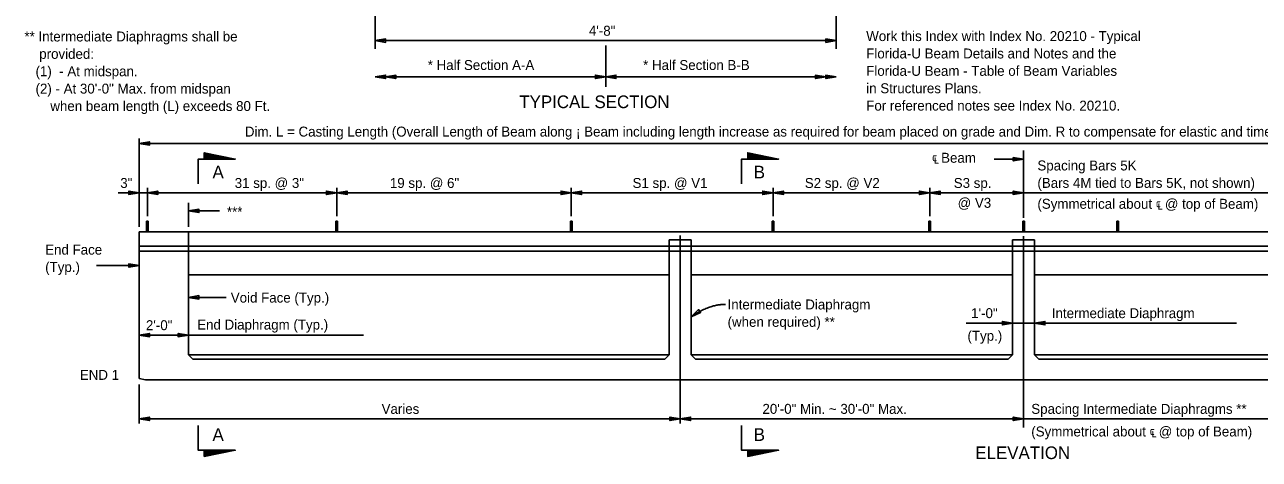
# Model space of a CAD drawing. Extents: x 120696.7 to 120732.7, y 120669.5 to 120684.8.
# Drawn here: x 120696.73 to 120709.23, y 120670.96 to 120675.36 of the extents above; entities that cross this region are included whole.
import ezdxf

# ---------------------------------------------------------------- set-up
doc = ezdxf.new("R2010")
doc.units = 0
for name, color, linetype in [('BeamConc', 7, 'Continuous'), ('BeamConc_h', 7, 'Continuous'), ('Dimension', 7, 'Continuous'), ('Miscellaneous', 7, 'Continuous'), ('Rebar', 7, 'Continuous'), ('TextStructures', 7, 'Continuous')]:
    doc.layers.add(name, color=color, linetype=linetype)

msp = doc.modelspace()

# ---------------------------------------------------------------- linework, layer by layer
at = {"layer": 'BeamConc'}
for p, q in [((120697.89, 120671.775), (120697.89, 120673.26)), ((120715.799, 120673.26), (120697.89, 120673.26)), ((120697.89, 120673.114), (120715.799, 120673.114)), ((120697.89, 120673.064), (120715.799, 120673.064)), ((120697.89, 120671.775), (120697.953, 120671.76)), ((120697.953, 120671.76), (120715.737, 120671.76))]:
    msp.add_line(p, q, dxfattribs=at)
at = {"layer": 'BeamConc_h'}
for p, q in [((120698.39, 120672.012), (120698.39, 120673.26)), ((120703.256, 120673.176), (120703.479, 120673.176)), ((120703.256, 120673.176), (120703.256, 120672.012)), ((120703.479, 120673.176), (120703.479, 120672.012)), ((120706.733, 120673.176), (120706.956, 120673.176)), ((120706.733, 120673.176), (120706.733, 120672.012)), ((120706.956, 120673.176), (120706.956, 120672.012)), ((120698.39, 120672.822), (120703.256, 120672.822)), ((120703.479, 120672.822), (120706.733, 120672.822)), ((120706.956, 120672.822), (120710.21, 120672.822)), ((120698.434, 120671.968), (120698.39, 120672.012)), ((120698.39, 120672.012), (120703.256, 120672.012)), ((120703.212, 120671.968), (120703.256, 120672.012)), ((120703.479, 120672.012), (120706.733, 120672.012)), ((120703.523, 120671.968), (120703.479, 120672.012)), ((120706.689, 120671.968), (120706.733, 120672.012)), ((120706.956, 120672.012), (120710.21, 120672.012)), ((120707, 120671.968), (120706.956, 120672.012)), ((120698.434, 120671.968), (120703.212, 120671.968)), ((120703.523, 120671.968), (120706.689, 120671.968)), ((120707, 120671.968), (120710.166, 120671.968))]:
    msp.add_line(p, q, dxfattribs=at)
at = {"layer": 'Dimension'}
for p, q in [((120700.28, 120675.113), (120700.28, 120675.569)), ((120704.947, 120675.113), (120704.947, 120675.471)), ((120700.28, 120675.194), (120704.947, 120675.194)), ((120700.28, 120674.828), (120704.947, 120674.828)), ((120697.89, 120673.31), (120697.89, 120674.204)), ((120697.89, 120674.153), (120715.799, 120674.153)), ((120698.862, 120673.996), (120698.549, 120674.051)), ((120698.549, 120674.045), (120698.862, 120673.996)), ((120698.862, 120673.996), (120698.549, 120674.036)), ((120698.549, 120674.027), (120698.862, 120673.996)), ((120698.862, 120673.996), (120698.549, 120674.018)), ((120704.364, 120673.996), (120704.052, 120674.051)), ((120704.052, 120674.045), (120704.364, 120673.996)), ((120704.364, 120673.996), (120704.052, 120674.036)), ((120704.052, 120674.027), (120704.364, 120673.996)), ((120704.364, 120673.996), (120704.052, 120674.018)), ((120698.549, 120674.008), (120698.862, 120673.996)), ((120704.052, 120674.008), (120704.364, 120673.996)), ((120706.844, 120673.994), (120706.547, 120673.994)), ((120697.677, 120673.653), (120709.712, 120673.653)), ((120697.974, 120673.417), (120697.974, 120673.704)), ((120699.89, 120673.417), (120699.89, 120673.704)), ((120702.265, 120673.417), (120702.265, 120673.704)), ((120704.309, 120673.417), (120704.309, 120673.704)), ((120705.894, 120673.417), (120705.894, 120673.704)), ((120698.39, 120673.31), (120698.39, 120673.551)), ((120698.703, 120673.47), (120698.39, 120673.47)), ((120697.457, 120672.918), (120697.89, 120672.918)), ((120698.77, 120672.595), (120698.39, 120672.595)), ((120708.999, 120672.335), (120706.262, 120672.335)), ((120697.89, 120672.212), (120700.162, 120672.212)), ((120697.89, 120671.318), (120697.89, 120671.712)), ((120697.89, 120671.366), (120709.957, 120671.366)), ((120698.549, 120671.036), (120698.862, 120671.047)), ((120698.862, 120671.047), (120698.549, 120671.026)), ((120698.549, 120671.016), (120698.862, 120671.047)), ((120698.862, 120671.047), (120698.549, 120671.007)), ((120698.549, 120670.999), (120698.862, 120671.047)), ((120698.862, 120671.047), (120698.549, 120670.992)), ((120704.052, 120671.036), (120704.364, 120671.047)), ((120704.364, 120671.047), (120704.052, 120671.026)), ((120704.052, 120671.016), (120704.364, 120671.047)), ((120704.364, 120671.047), (120704.052, 120671.007)), ((120704.052, 120670.999), (120704.364, 120671.047)), ((120704.364, 120671.047), (120704.052, 120670.992))]:
    msp.add_line(p, q, dxfattribs=at)
for points in [[(120700.28, 120675.194), (120700.384, 120675.176), (120700.384, 120675.212)], [(120704.947, 120675.194), (120704.843, 120675.212), (120704.843, 120675.176)], [(120700.28, 120674.828), (120700.384, 120674.81), (120700.384, 120674.845)], [(120700.384, 120674.828), (120700.488, 120674.81), (120700.488, 120674.845)], [(120702.613, 120674.828), (120702.509, 120674.845), (120702.509, 120674.81)], [(120702.613, 120674.828), (120702.717, 120674.845), (120702.717, 120674.81)], [(120704.843, 120674.828), (120704.738, 120674.845), (120704.738, 120674.81)], [(120704.947, 120674.828), (120704.843, 120674.845), (120704.843, 120674.81)], [(120697.89, 120674.153), (120697.994, 120674.136), (120697.994, 120674.171)], [(120706.844, 120673.994), (120706.74, 120674.011), (120706.74, 120673.976)], [(120697.89, 120673.653), (120697.786, 120673.636), (120697.786, 120673.671)], [(120697.974, 120673.653), (120698.078, 120673.636), (120698.078, 120673.671)], [(120699.89, 120673.653), (120699.786, 120673.636), (120699.786, 120673.671)], [(120699.89, 120673.653), (120699.994, 120673.636), (120699.994, 120673.671)], [(120702.265, 120673.653), (120702.161, 120673.636), (120702.161, 120673.671)], [(120702.265, 120673.653), (120702.369, 120673.636), (120702.369, 120673.671)], [(120704.309, 120673.653), (120704.204, 120673.636), (120704.204, 120673.671)], [(120704.309, 120673.653), (120704.413, 120673.636), (120704.413, 120673.671)], [(120705.893, 120673.653), (120705.789, 120673.636), (120705.789, 120673.671)], [(120705.893, 120673.653), (120705.998, 120673.636), (120705.998, 120673.671)], [(120706.844, 120673.653), (120706.74, 120673.636), (120706.74, 120673.671)], [(120706.844, 120673.653), (120706.777, 120673.665), (120706.777, 120673.642)], [(120698.39, 120673.47), (120698.494, 120673.453), (120698.494, 120673.488)], [(120697.89, 120672.918), (120697.786, 120672.935), (120697.786, 120672.9)], [(120698.39, 120672.595), (120698.494, 120672.577), (120698.494, 120672.613)], [(120703.479, 120672.397), (120703.574, 120672.443), (120703.554, 120672.472)], [(120706.733, 120672.335), (120706.629, 120672.352), (120706.629, 120672.317)], [(120706.956, 120672.335), (120707.06, 120672.317), (120707.06, 120672.352)], [(120697.89, 120672.212), (120697.994, 120672.195), (120697.994, 120672.23)], [(120698.39, 120672.212), (120698.286, 120672.195), (120698.286, 120672.23)], [(120697.89, 120671.366), (120697.994, 120671.348), (120697.994, 120671.384)], [(120703.367, 120671.366), (120703.263, 120671.348), (120703.263, 120671.384)], [(120703.367, 120671.366), (120703.472, 120671.348), (120703.472, 120671.384)], [(120706.844, 120671.366), (120706.74, 120671.384), (120706.74, 120671.348)]]:
    msp.add_lwpolyline(points, close=True, dxfattribs=at)
for points in [[(120698.487, 120673.746), (120698.487, 120673.996), (120698.862, 120673.996), (120698.549, 120674.059), (120698.549, 120673.996)], [(120703.989, 120673.746), (120703.989, 120673.996), (120704.364, 120673.996), (120704.052, 120674.059), (120704.052, 120673.996)], [(120698.487, 120671.297), (120698.487, 120671.047), (120698.862, 120671.047), (120698.549, 120670.985), (120698.549, 120671.047)], [(120703.989, 120671.297), (120703.989, 120671.047), (120704.364, 120671.047), (120704.052, 120670.985), (120704.052, 120671.047)]]:
    msp.add_lwpolyline(points, dxfattribs=at)
msp.add_open_spline([(120703.826, 120672.524), (120703.657, 120672.524), (120703.479, 120672.397)], degree=2, dxfattribs=at)
at = {"layer": 'Miscellaneous'}
for p, q in [((120702.613, 120674.726), (120702.613, 120675.145)), ((120706.844, 120673.399), (120706.844, 120674.083)), ((120703.367, 120671.318), (120703.367, 120673.222)), ((120706.844, 120671.278), (120706.844, 120673.216))]:
    msp.add_line(p, q, dxfattribs=at)
at = {"layer": 'Rebar'}
for p, q in [((120697.982, 120673.367), (120697.965, 120673.367)), ((120697.965, 120673.367), (120697.965, 120673.26)), ((120697.982, 120673.26), (120697.982, 120673.367)), ((120699.899, 120673.367), (120699.882, 120673.367)), ((120699.882, 120673.367), (120699.882, 120673.26)), ((120699.899, 120673.26), (120699.899, 120673.367)), ((120702.274, 120673.367), (120702.257, 120673.367)), ((120702.257, 120673.367), (120702.257, 120673.26)), ((120702.274, 120673.26), (120702.274, 120673.367)), ((120704.317, 120673.367), (120704.3, 120673.367)), ((120704.3, 120673.367), (120704.3, 120673.26)), ((120704.317, 120673.26), (120704.317, 120673.367)), ((120705.902, 120673.367), (120705.885, 120673.367)), ((120705.885, 120673.367), (120705.885, 120673.26)), ((120705.902, 120673.26), (120705.902, 120673.367)), ((120706.836, 120673.26), (120706.836, 120673.367)), ((120706.836, 120673.367), (120706.853, 120673.367)), ((120706.853, 120673.367), (120706.853, 120673.26)), ((120707.787, 120673.26), (120707.787, 120673.367)), ((120707.787, 120673.367), (120707.804, 120673.367)), ((120707.804, 120673.367), (120707.804, 120673.26))]:
    msp.add_line(p, q, dxfattribs=at)

# ---------------------------------------------------------------- texts
at = {"layer": 'Dimension'}
for s, p in [('** Intermediate Diaphragms shall be', (120696.728, 120675.186)), ('  Work this Index with Index No. 20210 - Typical', (120705.176, 120675.19)), ('    provided:', (120696.728, 120675.01)), ('  Florida-U Beam Details and Notes and the', (120705.176, 120675.014)), ('   (1)  - At midspan.', (120696.728, 120674.834)), ('  Florida-U Beam - Table of Beam Variables', (120705.176, 120674.838)), ('   (2) - At 30\'-0" Max. from midspan', (120696.728, 120674.658)), ('  in Structures Plans.', (120705.176, 120674.662)), ('       when beam length (L) exceeds 80 Ft.', (120696.728, 120674.482)), ('  For referenced notes see Index No. 20210.', (120705.176, 120674.486)), ('Spacing Bars 5K', (120706.984, 120673.88)), ('(Bars 4M tied to Bars 5K, not shown)', (120706.984, 120673.704)), ('End Face', (120696.938, 120673.028)), ('(Typ.)', (120696.938, 120672.852)), ('Intermediate Diaphragm ', (120703.847, 120672.473)), ('(when required) **', (120703.847, 120672.297))]:
    msp.add_text(s, height=0.1008, dxfattribs=at).set_placement(p)
at = {"layer": 'TextStructures'}
for s, height, p in [('4\'-8"', 0.1008, (120702.443, 120675.244)), ('* Half Section A-A', 0.1008, (120700.811, 120674.897)), ('* Half Section B-B', 0.1008, (120702.992, 120674.897)), ('TYPICAL SECTION', 0.128, (120701.738, 120674.511)), ('Dim. L = Casting Length (Overall Length of Beam along ¡ Beam including length increase as required for beam placed on grade and Dim. R to compensate for elastic and time dependent shortening effects)', 0.1008, (120698.96, 120674.223)), ('℄ Beam', 0.1008, (120705.917, 120673.958)), ('A', 0.128, (120698.632, 120673.8)), ('B', 0.128, (120704.112, 120673.8)), ('3"', 0.1008, (120697.698, 120673.703)), ('31 sp. @ 3"', 0.1008, (120698.857, 120673.703)), ('19 sp. @ 6"', 0.1008, (120700.428, 120673.703)), ('S1 sp. @ V1', 0.1008, (120702.885, 120673.703)), ('S2 sp. @ V2', 0.1008, (120704.629, 120673.703)), ('S3 sp.', 0.1008, (120706.137, 120673.703)), ('@ V3', 0.1008, (120706.177, 120673.502)), ('(Symmetrical about ℄ @ top of Beam)', 0.1008, (120706.984, 120673.492)), ('***', 0.1008, (120698.778, 120673.411)), ('Void Face (Typ.)', 0.1008, (120698.817, 120672.542)), ('1\'-0"', 0.1008, (120706.313, 120672.385)), ('Intermediate Diaphragm ', 0.1008, (120707.13, 120672.385)), ('2\'-0"', 0.1008, (120697.958, 120672.263)), ('End Diaphragm (Typ.)', 0.1008, (120698.477, 120672.269)), ('(Typ.)', 0.1008, (120706.276, 120672.156)), ('END 1', 0.1008, (120697.289, 120671.76)), ('Varies ', 0.1008, (120700.344, 120671.416)), ('20\'-0" Min. ~ 30\'-0" Max. ', 0.1008, (120704.2, 120671.416)), ('Spacing Intermediate Diaphragms **', 0.1008, (120706.922, 120671.416)), ('A', 0.128, (120698.632, 120671.142)), ('B', 0.128, (120704.112, 120671.142)), ('(Symmetrical about ℄ @ top of Beam)', 0.1008, (120706.922, 120671.187)), ('ELEVATION', 0.128, (120706.355, 120670.958))]:
    msp.add_text(s, height=height, dxfattribs=at).set_placement(p)

doc.saveas('drawing.dxf')
